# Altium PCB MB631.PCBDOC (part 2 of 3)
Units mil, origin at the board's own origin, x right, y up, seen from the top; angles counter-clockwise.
Board outline 4505 x 6805 mil, 4 copper layers (TopLayer, GND, VCC, BottomLayer); 273 components, 241 nets, 1286 pads, 636 vias.
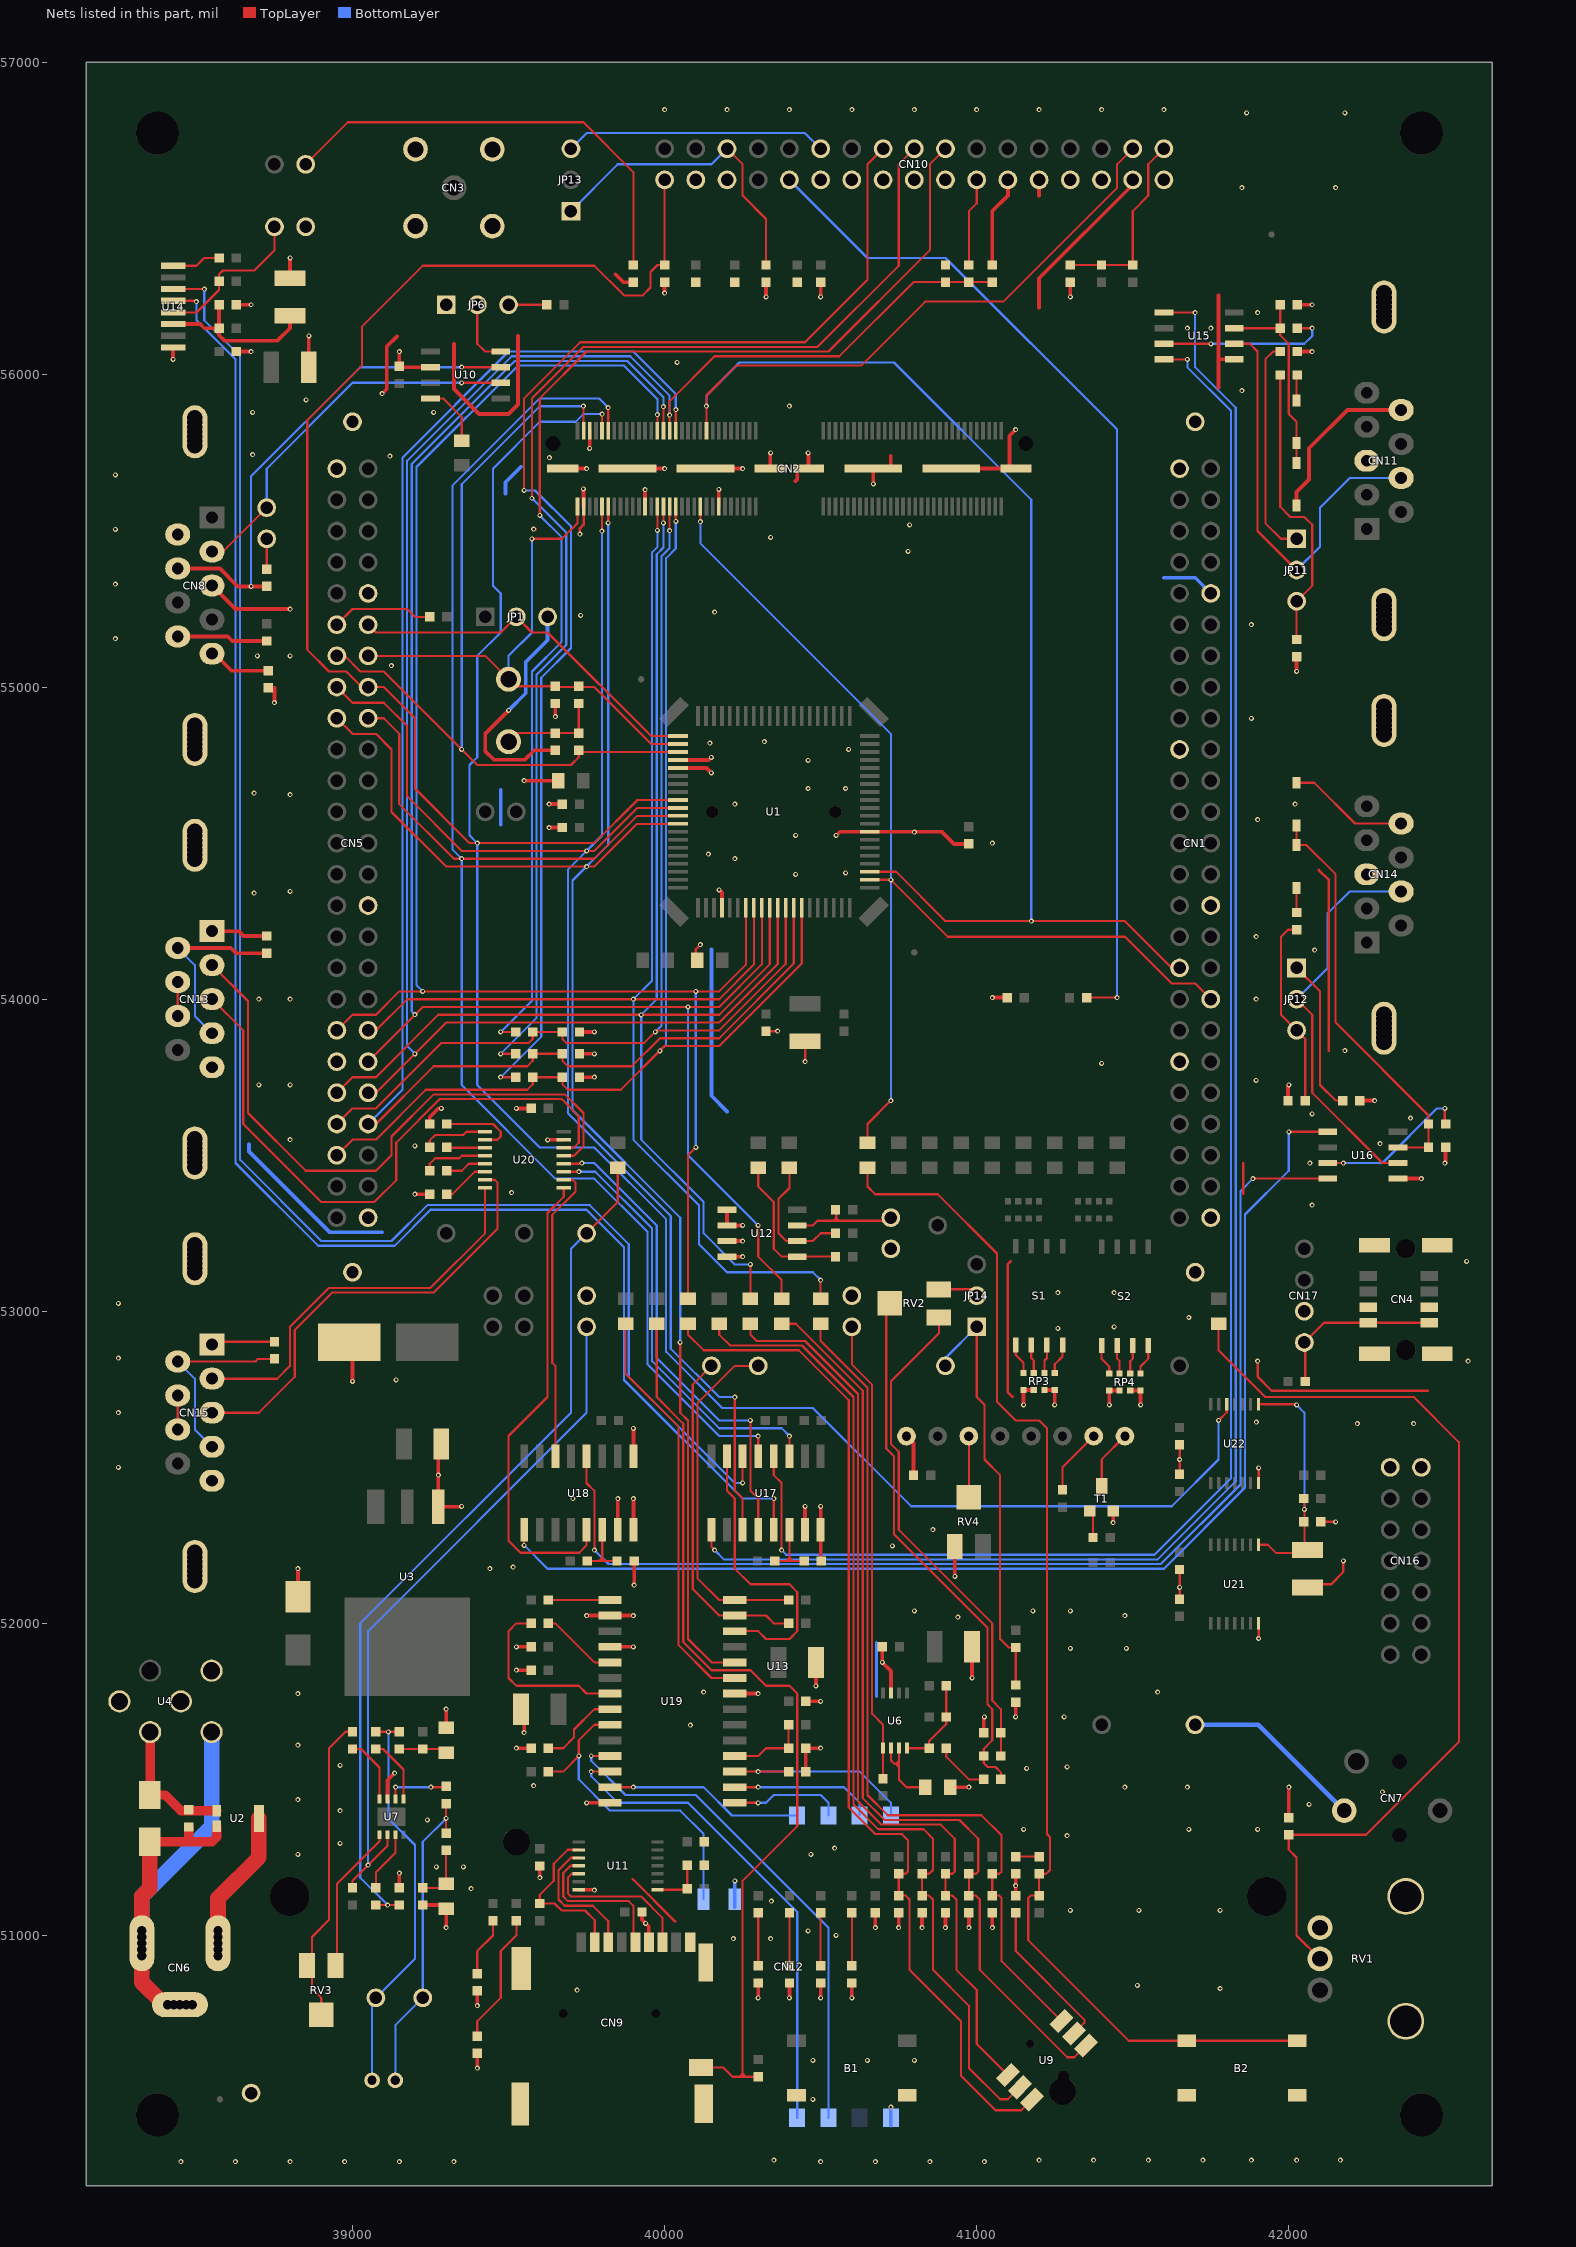
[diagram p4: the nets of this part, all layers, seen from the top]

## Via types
v1: diameter 16, hole 8, TopLayer to BottomLayer, tented both sides, 568 vias
v2: diameter 16, hole 8, TopLayer to BottomLayer, 68 vias

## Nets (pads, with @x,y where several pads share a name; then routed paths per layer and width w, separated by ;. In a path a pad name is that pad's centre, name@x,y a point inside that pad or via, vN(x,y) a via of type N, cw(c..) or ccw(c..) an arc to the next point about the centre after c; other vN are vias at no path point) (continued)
GND: B1.1 B1.4 B2.1 B2.4 C1.1 C4.2 C5.2 C6.2 C7.2 C8.2 C9.2 C10.2 C11.2 C12.2 C13.1 C16.1 C17.2 C18.2 C19.2 C20.2 C23.2 C24.1 C25.1 C26.1 C27.1 C28.1 C29.1 C30.2 C31.1 C32.1 C33.1 C34.1 C35.1 C36.1 C37.1 C38.1 C39.1 C40.1 C41.1 C42.1 C43.2 C45.2 C46.2 C47.2 C48.1 C49.2 C50.1 C53.2 C54.1 C55.2 C56.2 C57.2 C58.2 C59.1 C60.1 C61.2 C62.2 C63.2 C64.1 C65.1 C66.1 C67.1 C68.2 C69.1 C70.1 C71.2 C72.2 C73.2 C74.1 C75.1 C76.1 C77.2 CN1.1 CN1.10 CN1.19 CN1.30 CN1.39 CN1.50 CN2.4 CN2.5 CN2.24 CN2.48 CN2.G1 CN2.G2 CN2.G3 CN2.G4 CN3.1 CN3.2 CN3.3 CN3.4 CN4.3 CN4.G0 CN5.1 CN5.10 CN5.30 CN5.39 CN5.50 CN8.0 CN8.3 CN8.6 CN9.6 CN9.9 CN9.G1 CN9.G2 CN9.G3 CN9.G4 CN10.2 CN10.4 CN10.6 CN10.8 CN10.10 CN10.12 CN10.16 CN10.18 CN10.20 CN10.22 CN10.24 CN10.30 CN10.32 CN11.0 CN11.3 CN12.5 CN12.17 CN13.0 CN13.5 CN14.0 CN14.3 CN15.0 CN15.5 CN16.13 CN16.14 CN17.3 JP1.3 JP4.2 JP5.2 JP6.1 JP8.2 JP10.2 LD1.2 LD2.2 LD3.2 LD4.2 LD5.2 LD6.2 R11.1 R19.1 R25.1 R35.1 R45.1 R46.1 R48.1 R56.1 R66.1 R85.2 R90.2 R91.1 RP3.1 RP3.3 RP3.5 RP3.7 RP4.1 RP4.3 RP4.5 RP4.7 RV1.0 RV1.1 RV4.3 T1.1 TP4.1 TP11.1 TP12.1 TP13.1 TP14.1 U1.4 U1.5 U1.24 U1.48 U3.1 U4.4 U4.5 U4.6 U6.7 U7.7 U10.2 U11.7 U12.1 U12.2 U12.3 U12.4 U13.1 U14.8 U15.5 U16.5 U17.7 U17.8 U18.7 U18.8 U18.9 U19.2 U19.4 U19.14 U19.22 U20.15 U21.7 U22.7 | length 15563.9
  TopLayer w8: v1(39728.5,55490.16) 39728.5,55508.5 39740.55,55520.55 CN2.4@39740.55,55578.54 ; 39898.5,51180 40033.5,51045 ; R46.1@40100,54125 40100,54160 v1(40115,54175) ; C10.2@40325,53897.5 v1(40362.5,53897.5) ; v1(40450,53800) C7.2@40450,53865 ; 41108.5,53159.65 41100,53151.15 41100,52740.31 41115,52725.31 ; C74.1@41650,52077.5 C75.1@41650,52172.5 ; C65.1@41650,52477.5 C64.1@41650,52572.5 ; 41853.5,53376.5 41853.5,53475 ; v2(41900,52840) 41900,52790.31 41945.31,52745 42445,52745 ; v2(41903.54,51951.46) U21.7@41903.54,52000 ; U22.7@41903.54,52450 v2(41903.54,52498.54) ; C77.2@42070,52125 42134.69,52125 42175,52165.31 v2(42175,52200) ; 42095.4,54414.29 42128.5,54381.19 42128.5,53835 ; C76.1@42102.5,52325 v2(42150,52325)
  TopLayer w12: v1(38425,56050) U14.8@38425,56088.19 ; CN8.3@38550,55325 38625,55250 v1(38800,55250) ; C58.2@38625,56225 v1(38675,56225) ; C57.2@38627.5,56075 v1(38675,56075) ; v1(38750,54950) 38750,54997.5 ; C56.2@38800,56310 v1(38800,56375) ; C8.2@38825,52085 v1(38825,52175) ; C55.2@38860,56025 v1(38860,56125) ; v1(39000,52775) C11.2@39000,52900 ; v1(39095,55940) 39110,55955 39110,56091.16 39142.57,56123.73 ; U7.7@39112.2,51437.09 39112.2,51497.51 v1(39134.69,51520) ; C23.2@39150,51152.5 v1(39150,51200) ; C24.1@39150,56027.5 v1(39150,56075) ; C24.1@39152.5,56025 U10.2@39250,56025 ; v1(39200,53375) C54.1@39247.5,53375 ; R25.1@39225,51097.5 C20.2@39292.5,51097.5 ; C50.1@39247.5,53600 39247.5,53622.5 39275,53650 v1(39285,53650) ; C9.2@39275,52565 U3.1@39275,52373.82 39348.82,52373.82 v1(39350,52375) ; v1(39300,51025) C20.2@39300,51085 ; C19.2@39300,51665 v1(39300,51725) ; 39325,56100 39325,55955 39405,55875 39500,55875 39530,55905 39530,56125 ; v1(39400,50575) LD6.2@39400,50622.5 ; v1(39400,50775) LD5.2@39400,50822.5 ; v1(39500,54925) 39425,54850 39425,54795 39452.5,54767.5 39552.5,54767.5 39582.5,54797.5 C5.2@39650,54797.5 ; v1(39525,51600) C46.2@39572.5,51600 ; v1(39525,51850) C63.2@39572.5,51850 ; v1(39525,51925) C45.2@39572.5,51925 ; v1(39525,53650) C49.2@39572.5,53650 ; v1(39550,51650) C61.2@39550,51725 ; v1(39550,54700) C6.2@39660,54700 ; v1(39580,55506) v1@39585,55506 ; v1(39600,51185) C66.1@39600,51222.5 ; v1(39625,53549.41) U20.15@39676.97,53549.41 ; v1(39630,54550) C71.2@39672.5,54550 ; v1(39630,54625) C72.2@39672.5,54625 ; v1(39650,54905) C4.2@39650,54947.5 ; CN2.G1@39673.82,55700.2 39749.8,55700.2 v1(39750,55700) ; U11.7@39725,51146.46 39773.54,51146.46 v1(39775,51145) ; C36.1@39727.5,53750 v1(39775,53750) ; C35.1@39727.5,53825 v1(39775,53825) ; C34.1@39727.5,53895 v1(39775,53895) ; v1(39740,55635) 39740.55,55634.45 CN2.4@39740.55,55578.54 ; v1(39750,51425) U19.14@39825,51425 ; v1(39750,52025) v1(39900,52025) ; v1(39760,55765) 39760.24,55765.24 CN2.5@39760.24,55821.46 ; U19.4@39825,51925 v1(39900,51925) ; 39842.29,56323.02 39867.81,56297.5 C42.1@39900,56297.5 ; U18.7@39850,52300 v1(39850,52400) ; CN2.G2@39881.3,55700.2 39999.8,55700.2 v1(40000,55700) ; U18.8@39900,52300 v1(39900,52400) ; U18.9@39900,52535 v1(39900,52625) ; v1(39902.5,52122.5) R91.1@39902.5,52200 ; C12.2@39927.5,51075 39927.5,51050 39949.61,51027.89 CN9.6@39949.61,50953.35 ; CN2.24@39937.4,55578.54 v1(39937.4,55632.4) ; v1(40000,56262.5) C37.1@40000,56297.5 ; U1.5@40042.91,54740.75 40134.25,54740.75 v1(40150,54725) ; U1.4@40042.91,54766.34 40141.34,54766.34 v1(40150,54775) ; CN2.G3@40131.3,55700.2 40249.8,55700.2 v1(40250,55700) ; CN2.48@40173.62,55578.54 v1(40173.62,55633.62) ; v1(40175,54350) 40183.66,54341.34 U1.24@40183.66,54292.91 ; U12.4@40200,53175 v1(40250,53175) ; U12.3@40200,53225 v1(40250,53225) ; U12.1@40200,53325 U12.2@40200,53275 v1(40250,53275) ; U19.22@40225,51775 v1(40300,51775) ; v1(40300,50800) LD1.2@40300,50847.5 ; v1(40325,56250) C39.1@40325,56297.5 ; CN2.G4@40338.78,55700.2 40338.78,55748.78 v1(40340,55750) ; v1(40400,50800) LD2.2@40400,50847.5 ; 40419.69,55660 40425,55665.31 CN2.G1@40425,55695 ; U17.7@40450,52300 v1(40450,52375) ; C48.1@40452.5,51525 R85.2@40452.5,51600 v1(40500,51600) ; C47.2@40452.5,51750 v1(40500,51750) ; v1(40460,55750) 40461.22,55748.78 CN2.G1@40461.22,55700.2 ; v1(40485,51800) C62.2@40485,51875 ; v1(40500,50800) LD3.2@40500,50847.5 ; R90.2@40500,52202.5 v1(40500,52375) ; v1(40500,56250) R45.1@40500,56297.5 ; v1(40550,54525) 40561.02,54536.02 40888.98,54536.02 40927.5,54497.5 C73.2@40975,54497.5 ; v1(40600,50800) LD4.2@40600,50847.5 ; v1(40668.7,55651.3) CN2.G2@40668.7,55700.2 ; v1(40675,51025) C1.1@40675,51072.5 ; C13.1@40697.5,51925 v1(40697.5,51875) 40725.59,51846.91 U6.7@40725.59,51777.17 ; CN2.G2@40725,55700.2 40725,55740 ; v1(40750,51025) C26.1@40750,51072.5 ; U13.1@40775,52600 40797.5,52577.5 C30.2@40797.5,52475 ; v1(40825,51025) C25.1@40825,51072.5 ; v1(40900,51025) C27.1@40900,51072.5 ; C18.2@40915,51475 v1(40975,51475) ; CN2.G3@40918.7,55700.2 CN2.G4@41126.18,55700.2 ; v1(40929.72,52150.28) RV4.3@40929.72,52246.26 ; v1(40975,51025) C28.1@40975,51072.5 ; v1(40985,51825) C17.2@40985,51925 ; R19.1@41022.5,51650 41022.5,51697.5 v1(41025,51700) ; v1(41050,51025) C29.1@41050,51072.5 ; v1(41050,54005) C33.1@41097.5,54005 ; C32.1@41050,56352.5 41050,56525 41100,56575 CN10.12@41100,56625 ; CN2.G4@41105,55700.2 41105,55805 v1(41125,55825) ; R48.1@41125,51127.5 R11.1@41125,51197.5 ; v1(41125,51700) C16.1@41125,51747.5 ; v1(41150,52700) RP3.7@41150,52747.5 RP3.5@41183,52747.5 ; 41200,56215 41200,56309.69 CN10.4@41500,56609.69 ; 41200,56575 CN10.10@41200,56625 ; RP3.3@41217,52747.5 RP3.1@41250,52747.5 v1(41250,52700) ; v1(41300,56250) C31.1@41300,56297.5 ; v1(41425,52700) RP4.7@41425,52745.77 RP4.5@41458,52745.77 ; v1(41437.5,52322.5) T1.1@41437.5,52360 ; RP4.3@41492,52745.77 RP4.1@41525,52745.77 v1(41525,52700) ; 41775,55960 41775,56255 ; 41775,56050 U15.5@41825,56050 ; C70.1@41997.5,53675 41997.5,53722.5 v1(42000,53725) ; C68.2@42000,51377.5 v1(42000,51475) ; v1(42025,55050) C69.1@42025,55097.5 ; C59.1@42027.5,56075 v1(42075,56075) ; C43.2@42027.5,56225 v1(42075,56225) ; C60.1@42227.5,53675 v1(42275,53675) ; U16.5@42350,53425 v1(42425,53425) ; v1(42500,53475) 42502.5,53477.5 C53.2@42502.5,53525
  BottomLayer w10: 40678.5,51766.5 40678.5,51938.19
  BottomLayer w12: 38668.5,53535 38668.5,53511.5 38926.5,53253.5 39095,53253.5 ; 39475,54560 39475,54670 ; 39490,55620 39490,55656.45 39539.55,55706 ; v1(39500,54925) 39555,54980 39555,55080 39625,55150 JP1.3@39625,55225 ; 40150,54160 40150,53690.31 40200.31,53640 ; CN12.17@40225,51091.54 v1(40225,51175) ; CN12.5@40725,50390.75 v1(40725,50450) ; 41600,55350 41700,55350 CN1.10@41750,55300
  other v1: 38450,50275 38625,50275 38800,50275 38975,50275 39150,50275 39325,50275 40500,50275 40675,50275 40850,50275 41025,50275 40350,50280 41200,50280 41375,50280 41550,50280 41725,50280 41880,50280 42025,50280 42165,50280 40475,50475 40475,50600 40650,50600 40800,50600 39720,50825 40220,50990 40340,50990 40550,51000 40460,51015 39939.06,51038.44 40342.5,51110 39380,51150 41125,51160 39269,51220 39355,51220 38825,51260 40469,51260 40545,51280 38960,51295 39240,51370 38960,51400 38825,51435 41475,51475 41675,51475 39580,51480 38960,51545 38825,51610 40082.58,51673.58 38825,51775 40125,51780 39440,52175 39515,52180 39706,52400 39275,52475 38250,52500 38250,52675 39140,52780 42575,52840 38250,52850 38250,53025 42570,53160 42075,53340 39510,53380 42067.5,53475 39200,53530 42292.5,53537.5 38800,53550 42390,53619 42075,53632.5 38700,53725 38800,53725 41895,53740 41400,53794 42180,53835 38700,54000 38800,54000 41895,54000 42082.5,54157.5 41895,54200 38685,54340 38800,54345 40420,54400 40580,54405 40225,54450 40140,54465 41050,54500 40420,54525 40800,54535 41900,54575 40225,54625 42020,54625 38800,54655 38685,54660 40460,54675 40580,54675 40460,54765 40590,54800 40145,54820 40320,54825 41880,54900 39124.84,55069 38695,55100 38800,55100 38240,55155 41880,55200 39731,55230 40160,55240 38240,55330 40780,55435 40340,55480 38240,55505 40785,55520 38240,55680 39631,55735 39120,55740 38680,55745 38680,55880 39260,55880 40400,55900 38851.16,55920 41850,55950 40040,56040 41675,56150 41750,56150 41900,56200 41850,56600 42150,56600 41865,56840 42180,56840 40000,56850 40200,56850 40400,56850 40600,56850 40800,56850 41000,56850 41200,56850 41400,56850 41600,56850
  other v2: 41780,50830 41515,50840 41300,51080 41520,51080 41780,51080 41290,51320 41150,51340 41680,51340 41900,51340 42065,51420 42300,51460 41160,51535 41290,51540 41280,51700 41580,51780 41300,51920 41480,51920 40940,52020 41475,52025 40800,52040 41180,52040 41300,52040 41650,52115 40730,52248.5 40860,52300 41650,52525 42220,52640 42400,52640 41896.5,52645 41260,52945 41440,52950 41680,52980 41260,53060 41440,53060
NetB2_2: B2.2 B2.3 C2.2 R3.1 R4.2 | length 3942.8
  TopLayer w7: R4.2@40650,53460 40650,53400 40675,53375 40875,53375 41065,53185 41065,52710 41125,52650 41200,52650 41225,52625 41225,51325 41235,51315 41235,51210 41222.5,51197.5 C2.2@41200,51197.5 R3.1@41200,51127.5 41172.5,51127.5 41165,51120 41165,50985 41487.5,50662.5 B2.3@42037.5,50662.5
NetC2_1: C2.1 R11.2 | length 75
  TopLayer w7: R11.2@41125,51252.5 C2.1@41200,51252.5
NetC5_1: C5.1 R2.1 R98.2 X1.1 | length 331.4
  TopLayer w7: X1.1@39500,54825 39527.5,54852.5 R98.2@39725,54852.5 R2.1@39725,54947.5
NetC15_2: C15.2 R31.1 | length 177.5
  TopLayer w7: R31.1@40902.5,51600 40902.5,51572.5 40975,51500 C15.2@41022.5,51500
NetC19_1: C19.1 R22.1 R23.1 | length 147.5
  TopLayer w7: R23.1@39150,51597.5 C19.1@39297.5,51597.5
NetC20_1: C20.1 R24.1 R25.2 | length 175
  TopLayer w7: R25.2@39225,51152.5 C20.1@39292.5,51152.5 ; C20.1@39300,51165 R24.1@39300,51272.5
NetC21_2: C21.2 U7.5 | length 210.2
  TopLayer w7: C21.2@39075,51597.5 39097.5,51597.5 39163.39,51531.61 U7.5@39163.39,51437.09
NetC22_2: C22.2 U7.6 | length 197.6
  TopLayer w7: U7.6@39137.8,51437.09 v1(39137.8,51475) ; v1(39251.25,51475) C22.2@39297.5,51475
  BottomLayer w7: v1(39137.8,51475) v1(39251.25,51475)
NetC42_2: C42.2 JP9.2 | length 1469.7
  TopLayer w7: JP9.2@38850,56675 38985,56810 39740,56810 39900,56650 C42.2@39900,56352.5
NetC44_1: C44.1 U19.7 | length 588.6
  TopLayer w7: C44.1@39572.5,52000 39525,52000 39500,51975 39500,51825 39525,51800 39725,51800 39750,51775 U19.7@39835,51775
NetC48_2: C48.2 CN12.1 U19.17 | length 679.7
  TopLayer w7: U19.17@40225,51525 C48.2@40397.5,51525
  BottomLayer w7: v1(40300,51525) 40625,51525 40725,51425 CN12.1@40725,51384.25
NetC50_2: C50.2 U20.2 | length 252.2
  TopLayer w7: C50.2@39302.5,53600 39450,53600 39475,53575 39475,53560 39464.41,53549.41 U20.2@39425,53549.41
NetC52_1: C52.1 U20.1 | length 211.4
  TopLayer w7: C52.1@39247.5,53525 39247.5,53547.5 39265,53565 39355,53565 39365,53575 U20.1@39425,53575
NetC52_2: C52.2 U20.3 | length 121.3
  TopLayer w7: C52.2@39303.68,53523.82 U20.3@39425,53523.82
NetC54_2: C54.2 U20.6 | length 152.3
  TopLayer w7: C54.2@39302.5,53375 39320,53375 39392.05,53447.05 U20.6@39425,53447.05
NetCN6_1: CN6.1 U2.1 | length 474.2
  TopLayer w50: CN6.1@38569.09,50955 38569.09,51119.09 38700,51250 U2.1@38700,51375
NetCN6_3: C3.2 CN6.2 CN6.3 U2.2 U4.2 Z1.1 | length 1696.7
  TopLayer w30: Z1.1@38360,51300.2 38549.8,51300.2 38565,51315.39 U2.2@38565,51350 ; 38475,51300.2 C3.2@38475,51347.5
  TopLayer w50: Z1.1@38350,51315 38350,51150 38325,51125 38325,50850 38395,50780 CN6.2@38455,50780
  BottomLayer w30: CN6.3@38325,50985 CN6.3@38325,50995
  BottomLayer w50: CN6.3@38325,50985 38325,51125 38548.43,51348.43 U4.2@38548.43,51651.57
NetCN7_10: CN7.10 U5.1 | length 591.9
  BottomLayer w15: U5.1@41699.61,51675 41902.56,51675 CN7.10@42177.56,51400
NetCN9_10: CN9.10 R100.1 R101.1 | length 3012
  TopLayer w7: R101.1@39975,52960 39975,52725 40060,52640 40060,51940 40150,51850 40275,51850 40325,51800 40400,51800 40425,51775 40425,51350 40250,51175 40250,50547.5 ; CN9.10@40116.93,50576.77 40188.23,50576.77 40217.5,50547.5 R100.1@40300,50547.5 ; 40240,50547.5 40250,50557.5 40260,50547.5
NetCN10_14: CN10.14 R61.1 | length 282.9
  TopLayer w7: R61.1@40975,56352.5 40975,56525 41000,56550 CN10.14@41000,56625
NetCN10_26: CN10.26 R63.1 | length 3298.9
  TopLayer w7: R63.1@41352.5,54005 v1(41450,54005)
  BottomLayer w7: CN10.26@40400,56625 40650,56375 40900,56375 41450,55825 v1(41450,54005)
NetCN12_2: CN12.2 U19.16 | length 461.5
  TopLayer w7: U19.16@40225,51475 v1(40300,51475)
  BottomLayer w7: v1(40300,51475) 40575,51475 40625,51425 CN12.2@40625,51384.25
NetCN12_3: CN12.3 U19.15 | length 361.5
  TopLayer w7: U19.15@40225,51425 v1(40300,51425)
  BottomLayer w7: v1(40300,51425) 40325,51425 40350,51450 40500,51450 40525,51425 CN12.3@40525,51384.25
NetCN13_7: CN13.7 CN13.8 | length 109
  TopLayer w7: CN13.8@38440,53946 CN13.7@38440,54055
NetCN15_7: CN15.7 CN15.8 | length 109
  TopLayer w7: CN15.8@38440,52621 CN15.7@38440,52730
NetD1_1: CN11.9 D1.1 | length 546
  TopLayer w12: D1.1@42025,55581.5 42025,55625 42065,55665 42065,55765 42188,55888 CN11.9@42360,55888
NetD2_1: CN14.9 D2.1 | length 389.1
  TopLayer w7: D2.1@42025,54693.5 42081.5,54693.5 42212,54563 CN14.9@42360,54563
NetJP4_1: JP4.1 R27.1 U6.1 | length 1488.9
  TopLayer w7: JP4.1@40600,52950 40600,52830 40665,52765 40665,51710 40700,51675 R27.1@40700,51502.5
NetJP6_3: JP6.3 R33.1 | length 122.5
  TopLayer w7: JP6.3@39500,56225 R33.1@39622.5,56225
NetJP10_1: JP10.1 R81.1 U14.5 | length 512
  TopLayer w7: U14.5@38425,56200.39 38500.39,56200.39 38572.5,56272.5 38572.5,56322.5 38585,56335 38685,56335 38750,56400 JP10.1@38750,56475
NetJP11_1: C59.2 JP11.1 | length 703.6
  TopLayer w7: C59.2@41972.5,56075 41950,56075 41925,56050 41925,55525 41975,55475 JP11.1@42025,55475
NetJP12_1: C60.2 JP12.1 | length 499.3
  TopLayer w7: JP12.1@42025,54100 42100,54025 42100,53725 42150,53675 C60.2@42172.5,53675
NetJP13_1: C39.2 CN10.29 JP13.1 | length 1007.1
  TopLayer w7: CN10.29@40200,56725 40250,56675 40250,56575 40325,56500 C39.2@40325,56352.5
  BottomLayer w7: JP13.1@39700,56525 39850,56675 40150,56675 CN10.29@40200,56725
NetJP13_3: CN10.23 JP13.3 | length 841.4
  BottomLayer w7: JP13.3@39700,56725 39750,56775 40450,56775 CN10.23@40500,56725
NetR5_2: C68.1 R5.2 RV1.2 | length 3044.3
  TopLayer w7: R5.2@41775,52960 41775,52875 41925,52725 42400,52725 42545,52580 42545,51620 42247.5,51322.5 C68.1@42000,51322.5 42000,51275 42025,51250 42025,51000 RV1.2@42100,50925
NetR6_2: CN4.4 CN17.4 R6.2 | length 548.4
  TopLayer w7: CN17.4@42050,52900 42112.99,52962.99 CN4.4@42449.8,52962.99 ; R6.2@42052.5,52775 CN17.4@42052.5,52897.5
NetR12_1: LD4.1 R12.1 | length 170
  TopLayer w7: LD4.1@40600,50902.5 R12.1@40600,51072.5
NetR13_1: LD3.1 R13.1 | length 170
  TopLayer w7: LD3.1@40500,50902.5 R13.1@40500,51072.5
NetR14_1: LD2.1 R14.1 | length 170
  TopLayer w7: LD2.1@40400,50902.5 R14.1@40400,51072.5
NetR15_1: LD1.1 R15.1 | length 170
  TopLayer w7: LD1.1@40300,50902.5 R15.1@40300,51072.5
NetR16_1: CN5.11 R16.1 | length 328.6
  TopLayer w7: CN5.11@38950,55200 39000,55250 39175,55250 39200,55225 R16.1@39247.5,55225
NetR17_1: LD5.1 R17.1 | length 190.7
  TopLayer w7: LD5.1@39400,50877.5 39400,50950 39450,51000 R17.1@39450,51047.5
NetR18_1: LD6.1 R18.1 | length 421.8
  TopLayer w7: LD6.1@39400,50677.5 39400,50725 39475,50800 39475,50950 39525,51000 R18.1@39525,51047.5
NetR19_2: R19.2 R32.1 RV2.3 | length 1614.4
  TopLayer w7: RV2.3@40878.74,52979.72 40878.74,52928.74 40725,52775 40725,52575 40750,52550 40750,52300 41050,52000 41050,51752.5 41077.5,51725 R32.1@41077.5,51575
NetR26_1: R26.1 RV3.1 RV3.2 | length 985.7
  TopLayer w7: RV3.2@38900,50746.26 38900,50800 38870,50830 38870,50995 38925,51050 38925,51600 38977.5,51652.5 R26.1@39000,51652.5
NetR30_2: C16.2 JP14.1 R30.2 TP5.1 | length 1393.9
  TopLayer w7: JP14.1@41000,52965 41000,52725 41025,52700 41025,52525 41075,52475 41075,51950 41102.5,51922.5 R30.2@41125,51922.5 C16.2@41125,51802.5
  BottomLayer w7: TP5.1@40900,52825 40900,52850 JP14.1@41000,52950
NetR31_2: C14.1 R29.1 R31.2 U6.4 | length 293.5
  TopLayer w7: U6.4@40776.77,51600 R31.2@40847.5,51600 40847.5,51622.5 40902.5,51677.5 R29.1@40902.5,51800
NetR39_1: C25.2 R39.1 R49.2 U9.2 | length 3212.5
  TopLayer w7: R39.1@40175,52960 40175,52925 40210,52890 40440,52890 40605,52725 40605,51420 40685,51340 40830,51340 40860,51310 40860,51210 40847.5,51197.5 R49.2@40825,51197.5 C25.2@40825,51127.5 40847.5,51127.5 40860,51115 40860,50890 40975,50775 40975,50575 41075,50475 41100,50475 U9.2@41138.7,50513.7
NetR40_1: C26.2 R40.1 R50.1 U9.3 | length 3339.7
  TopLayer w7: R40.1@40075,52960 40075,52925 40125,52875 40430,52875 40590,52715 40590,51410 40675,51325 40760,51325 40780,51305 40780,51205 40772.5,51197.5 R50.1@40750,51197.5 C26.2@40750,51127.5 40772.5,51127.5 40785,51115 40785,50890 40950,50725 40950,50550 41060,50440 41142.95,50440 U9.3@41177.67,50474.73
NetR41_1: C27.2 R41.1 R51.1 U9.1 | length 3002.2
  TopLayer w7: R41.1@40275,52960 40275,52925 40295,52905 40450,52905 40620,52735 40620,51430 40695,51355 40885,51355 40930,51310 40930,51205 40922.5,51197.5 R51.1@40900,51197.5 C27.2@40900,51127.5 40922.5,51127.5 40935,51115 40935,50890 41000,50825 41000,50652.4 U9.1@41099.73,50552.67
NetR42_1: C28.2 R42.1 R52.1 U9.4 | length 3022.9
  TopLayer w7: R42.1@40375,52960 40420,52960 40635,52745 40635,51440 40705,51370 40945,51370 41005,51310 41005,51205 40997.5,51197.5 R52.1@40975,51197.5 C28.2@40975,51127.5 40997.5,51127.5 41010,51115 41010,50890 41290,50610 41312.95,50610 U9.4@41350.27,50647.33
NetR43_1: R43.1 U10.4 | length 199.9
  TopLayer w7: U10.4@39250,55925 39290,55925 39350,55865 R43.1@39350,55790
NetR44_1: C29.2 R44.1 R53.1 U9.6 | length 2781.6
  TopLayer w7: R44.1@40500,52960 40500,52905 40650,52755 40650,51450 40715,51385 41015,51385 41080,51320 41080,51205 41072.5,51197.5 R53.1@41050,51197.5 C29.2@41050,51127.5 41072.5,51127.5 41080,51120 41080,50917.6 U9.6@41272.33,50725.27
NetR48_2: R48.2 U9.5 | length 491.3
  TopLayer w7: R48.2@41125,51072.5 41125,50950 41345,50730 41345,50720 U9.5@41311.3,50686.3
NetR54_2: JP7.1 R54.2 | length 97.5
  TopLayer w7: R54.2@38725,55377.5 JP7.1@38725,55475
NetR55_2: CN8.9 R55.2 | length 291
  TopLayer w12: CN8.9@38440,55162 38600,55162 38614.5,55147.5 R55.2@38725,55147.5
NetR56_2: CN8.5 R56.2 | length 191.7
  TopLayer w12: CN8.5@38560,55105 38612.5,55052.5 R56.2@38730,55052.5
NetR62_2: CN10.15 R62.2 | length 3979.7
  TopLayer w7: v1(39475,53895) R62.2@39522.5,53895 ; v1(39600,55550) 39600,55925 39750,56075 40525,56075 40850,56400 40850,56675 CN10.15@40900,56725
  BottomLayer w7: v1(39475,53895) 39575,53995 39575,55050 39670,55145 39670,55480 v1(39600,55550)
NetR64_2: CN10.17 R64.2 | length 4026.8
  TopLayer w7: v1(39475,53825) R64.2@39522.5,53825 ; v1(39575,55605) 39575,55925 39740,56090 40490,56090 40750,56350 40750,56675 CN10.17@40800,56725
  BottomLayer w7: v1(39475,53825) 39590,53940 39590,55040 39685,55135 39685,55495 v1(39575,55605)
NetR65_2: CN10.19 R65.2 | length 4096.4
  TopLayer w7: v1(39475,53750) R65.2@39522.5,53750 ; v1(39550,55630) 39550,55925 39730,56105 40450,56105 40650,56305 40650,56675 CN10.19@40700,56725
  BottomLayer w7: v1(39475,53750) 39605,53880 39605,55030 39700,55125 39700,55515 39585,55630 v1(39550,55630)
NetR67_1: C31.2 CN10.1 R60.1 R67.1 | length 613.9
  TopLayer w7: C31.2@41300,56352.5 R60.1@41500,56352.5 41500,56525 41550,56575 41550,56675 CN10.1@41600,56725
NetR70_2: R70.2 R90.1 U17.6 | length 223.3
  TopLayer w7: R70.2@40352.5,52200 R90.1@40447.5,52200 ; 40390,52200 40400,52210 40410,52200 ; 40400,52200 U17.6@40400,52300
NetR71_2: R71.2 R91.2 U18.6 | length 223.3
  TopLayer w7: R71.2@39752.5,52200 R91.2@39847.5,52200 ; 39790,52200 39800,52210 39810,52200 ; 39800,52200 U18.6@39800,52300
NetR79_1: D3.2 R79.1 | length 79
  TopLayer w7: D3.2@42025,55918.5 R79.1@42025,55997.5
NetR79_2: C69.2 JP11.3 R79.2 | length 937
  TopLayer w7: R79.2@41972.5,56000 41972.5,55577.5 42005.55,55544.45 42050.55,55544.45 42075,55520 42075,55325 JP11.3@42025,55275 C69.2@42025,55152.5
NetR80_1: D4.2 R80.1 | length 79
  TopLayer w7: R80.1@42025,54277.5 D4.2@42025,54356.5
NetR80_2: C70.2 JP12.3 R80.2 | length 616.4
  TopLayer w7: R80.2@42025,54222.5 41997.5,54222.5 41975,54200 41975,53950 42052.5,53872.5 C70.2@42052.5,53675
NetR87_2: R87.2 U19.1 | length 197.5
  TopLayer w7: R87.2@39627.5,52075 U19.1@39825,52075
NetR88_2: R88.2 U14.1 | length 157.9
  TopLayer w7: U14.1@38425,56350 38500,56350 38525,56375 R88.2@38572.5,56375
NetR89_2: C56.1 C58.1 R89.2 U14.6 | length 541.7
  TopLayer w12: U14.6@38425,56162.99 38512.01,56162.99 38525,56150 R89.2@38572.5,56150 ; C58.1@38572.5,56225 38572.5,56127.5 38590,56110 38760,56110 38800,56150 C56.1@38800,56190
NetR92_1: CN13.4 CN13.6 R92.1 | length 610.4
  TopLayer w12: CN13.6@38440,54164 38610,54164 38626.5,54147.5 R92.1@38725,54147.5
  BottomLayer w7: CN13.6@38440,54164 38495,54109 38495,53946 CN13.4@38550,53891
NetR92_2: CN13.1 R92.2 | length 181.4
  TopLayer w12: CN13.1@38550,54218 38635,54218 38650.5,54202.5 R92.2@38725,54202.5
NetR93_1: CN15.4 CN15.6 R93.1 | length 632.1
  TopLayer w7: CN15.6@38440,52839 38689,52839 38697.5,52847.5 R93.1@38750,52847.5
  BottomLayer w7: CN15.6@38440,52839 38495,52784 38495,52621 CN15.4@38550,52566
NetR93_2: CN15.1 R93.2 | length 202.5
  TopLayer w7: CN15.1@38547.5,52902.5 R93.2@38750,52902.5
NetR104_2: R104.2 U13.7 | length 213.9
  TopLayer w7: R104.2@41275,52427.5 41275,52500 U13.7@41375,52600
NetRP4_2: RP4.2 S2.7 | length 99.6
  TopLayer w7: RP4.2@41525,52800.77 41525,52823.27 41550,52848.27 S2.7@41550,52890
NetRP4_4: RP4.4 S2.5 | length 92.5
  TopLayer w7: RP4.4@41492,52800.77 41492,52840.27 41500,52848.27 S2.5@41500,52890
NetRP4_6: RP4.6 S2.3 | length 92.5
  TopLayer w7: S2.3@41450,52890 41450,52848.27 41458,52840.27 RP4.6@41458,52800.77
NetRP4_8: RP4.8 S2.1 | length 99.6
  TopLayer w7: S2.1@41400,52890 41400,52848.27 41425,52823.27 RP4.8@41425,52800.77
NetRV2_1: JP14.2 RV2.1 | length 138.1
  TopLayer w7: RV2.1@40870.28,53070.28 40979.72,53070.28 JP14.2@41000,53050
NetRV2_2: C15.1 R32.2 RV2.2 | length 1719.6
  TopLayer w7: RV2.2@40710,53030 40710,52560 40735,52535 40735,52285 41035,51985 41035,51740 41050,51725 41050,51625 41022.5,51597.5 41022.5,51552.5 41035,51540 41060,51540 41077.5,51522.5 C15.1@41077.5,51500
NetRV3_3: RV3.3 U7.1 | length 484.5
  TopLayer w7: RV3.3@38950,50895 38950,51165 39086.61,51301.61 U7.1@39086.61,51322.91
NetRV4_2: RV4.2 U13.3 | length 196.3
  TopLayer w7: RV4.2@40975,52403.74 U13.3@40975,52600
NetS1_1: RP3.8 S1.1 | length 99.6
  TopLayer w7: S1.1@41125,52891.73 41125,52860 41150,52835 RP3.8@41150,52802.5
NetS1_3: RP3.6 S1.3 | length 92.5
  TopLayer w7: S1.3@41175,52891.73 41175,52850 41183,52842 RP3.6@41183,52802.5
NetS1_5: RP3.4 S1.5 | length 92.5
  TopLayer w7: RP3.4@41217,52802.5 41217,52842 41225,52850 S1.5@41225,52891.73
NetS1_7: RP3.2 S1.7 | length 99.6
  TopLayer w7: RP3.2@41250,52802.5 41250,52830 41275,52855 S1.7@41275,52891.73
NetT1_2: R103.1 T1.2 | length 82.5
  TopLayer w7: R103.1@41372.5,52275 T1.2@41372.5,52357.5
NetTP6_1: C23.1 R20.1 R21.2 TP6.1 | length 2815.5
  TopLayer w7: R20.1@39075,51097.5 C23.1@39150,51097.5 ; TP6.1@39750,53250 39850,53350 R21.2@39850,53460
  BottomLayer w7: v1(39112.5,51097.5) 39025,51185 39025,52000 39700,52675 39700,53200 TP6.1@39750,53250
NetU2_3: C3.1 U2.3 U4.1 Z1.2 | length 438.1
  TopLayer w30: U4.1@38351.57,51651.57 38351.57,51451.38 Z1.2@38350,51449.8 38400.2,51449.8 38450,51400 U2.3@38565,51400
NetU6_2: C18.1 U6.2 U6.3 | length 292.5
  TopLayer w7: U6.2@40725.59,51600 40725.59,51560.59 40736.18,51550 40751.18,51550 ; 40751.18,51540 40741.18,51550 40751.18,51560 ; U6.3@40751.18,51600 40751.18,51498.82 40775,51475 C18.1@40835,51475
NetU7_2: JP5.1 R28.2 U7.2 | length 2231.8
  TopLayer w7: R28.2@39000,51152.5 39000,51175 39112.2,51287.2 U7.2@39112.2,51322.91
  BottomLayer w7: v1(39050,51225) 39050,51975 39750,52675 JP5.1@39750,52950
NetU7_3: R20.2 U7.3 | length 196.4
  TopLayer w7: R20.2@39075,51152.5 39075,51202.57 39137.8,51265.37 U7.3@39137.8,51322.91
NetU7_8: R26.2 U7.8 | length 212.4
  TopLayer w7: R26.2@39000,51597.5 39027.5,51597.5 39086.61,51538.39 U7.8@39086.61,51437.09
NetU8_1: C22.1 R24.2 TP8.1 U8.1 | length 1001.7
  TopLayer w7: R24.2@39300,51327.5 C22.1@39300,51422.5
  BottomLayer w7: U8.1@39137.4,50535.63 39137.4,50712.4 TP8.1@39225,50800 39225,51300 v1(39300,51375)
NetU8_2: C21.1 R23.2 TP7.1 U8.2 | length 1284
  TopLayer w7: C21.1@39075,51652.5 R23.2@39150,51652.5
  BottomLayer w7: U8.2@39062.6,50535.63 39062.6,50787.6 39200,50925 39200,51290 39115,51375 v1(39115,51652.5)
NetU10_6: CN8.2 JP7.2 U10.6 | length 1222.3
  TopLayer w7: CN8.2@38550,55434 38584,55434 JP7.2@38725,55575 ; v1(39350,55975) U10.6@39475,55975
  BottomLayer w7: JP7.2@38725,55575 38725,55700 39000,55975 v1(39350,55975)
NetU10_7: CN8.7 R54.1 U10.7 | length 1606.3
  TopLayer w7: v1(39350,56025) U10.7@39475,56025
  TopLayer w12: CN8.7@38440,55380 38575,55380 38632.5,55322.5 R54.1@38725,55322.5
  BottomLayer w7: v1(38675,55322.5) 38675,55675 39025,56025 v1(39350,56025)
NetU10_8: JP6.2 U10.8 | length 210.4
  TopLayer w7: JP6.2@39400,56225 39400,56100 39425,56075 U10.8@39475,56075
NetU11_2: CN9.2 R57.1 U11.2 | length 513.5
  TopLayer w7: U11.2@39725,51274.41 39689.41,51274.41 39645,51230 39645,51175 39600,51130 R57.1@39600,51102.5 39647.5,51102.5 39670,51080 39745,51080 39776.38,51048.62 CN9.2@39776.38,50978.35
NetU11_3: CN9.3 U11.3 | length 430.9
  TopLayer w7: U11.3@39725,51248.82 39700,51248.82 39660,51208.82 39660,51115 39680,51095 39770,51095 39819.69,51045.31 CN9.3@39819.69,50978.35
NetU11_4: CN9.5 U11.4 | length 507.4
  TopLayer w7: U11.4@39725,51223.23 39698.23,51223.23 39675,51200 39675,51125 39690,51110 39885,51110 39900,51095 CN9.5@39900,50959.65
NetU11_5: CN9.7 U11.5 | length 529.2
  TopLayer w7: U11.5@39725,51197.64 39702.64,51197.64 39690,51185 39690,51135 39700,51125 39925,51125 39992.91,51057.09 CN9.7@39992.91,50953.35
NetU11_8: R34.1 R35.2 U11.8 | length 167
  TopLayer w7: U11.8@39976.97,51146.46 R34.1@40068.96,51146.46 ; R34.1@40072.5,51150 R35.2@40072.5,51225
NetU12_5: R38.2 R96.2 U12.5 | length 488.6
  TopLayer w7: R96.2@40300,53460 40300,53400 40350,53350 40350,53200 40375,53175 R38.2@40547.5,53175
NetU12_6: R37.2 R95.2 U12.6 | length 427.7
  TopLayer w7: R95.2@40400,53460 40400,53395 40365,53360 40365,53250 40390,53225 40475,53225 40500,53250 R37.2@40547.5,53250
NetU12_7: JP8.1 R36.2 U12.7 | length 372
  TopLayer w7: U12.7@40425,53275 40475,53275 40490,53290 JP8.1@40730,53290 ; 40540,53290 40550,53300 40560,53290 ; 40550,53290 R36.2@40550,53322.5
NetU13_8: T1.3 U13.8 | length 190.9
  TopLayer w7: T1.3@41400.5,52440 41400.5,52525.5 U13.8@41475,52600
NetU15_3: R72.1 U15.3 | length 557.9
  TopLayer w7: U15.3@41600,56100 v1(41750,56100) ; R72.1@42027.5,56150 v1(42075,56150)
  BottomLayer w7: v1(41750,56100) 42050,56100 42075,56125 v1(42075,56150)
NetU15_6: CN11.7 JP11.2 U15.6 | length 1367.5
  TopLayer w7: U15.6@41825,56100 41875,56100 41900,56075 41900,55500 JP11.2@42025,55375
  BottomLayer w7: JP11.2@42025,55375 42100,55450 42100,55575 42195,55670 CN11.7@42360,55670
NetU15_7: C43.1 D1.2 D3.1 R72.2 U15.7 | length 675.7
  TopLayer w7: U15.7@41825,56150 R72.2@41972.5,56150 ; C43.1@41972.5,56225 41972.5,56127.5 42000,56100 42000,55875 42025,55850 D1.2@42025,55718.5
NetU16_3: R73.1 U16.3 | length 495
  TopLayer w7: U16.3@42125,53475 v1(42175,53475) ; R73.1@42500,53602.5 v1(42500,53650)
  BottomLayer w7: v1(42175,53475) 42300,53475 42475,53650 v1(42500,53650)
NetU16_6: CN14.7 JP12.2 U16.6 | length 1269.3
  TopLayer w7: JP12.2@42025,54000 42075,53950 42075,53700 42300,53475 U16.6@42350,53475
  BottomLayer w7: JP12.2@42025,54000 42125,54100 42125,54275 42195,54345 CN14.7@42360,54345
NetU16_7: C53.1 D2.2 D4.1 R73.2 U16.7 | length 1316
  TopLayer w7: D4.1@42025,54493.5 42056.5,54493.5 42150,54400 42150,53925 42447.5,53627.5 C53.1@42447.5,53525 U16.7@42350,53525 ; D4.1@42025,54500 D2.2@42025,54556.5
NetU17_1: U15.1 U17.1 | length 5754
  TopLayer w7: U17.1@40150,52300 40150,52245 v1(40160,52235) ; U15.1@41600,56200 v1(41700,56200)
  BottomLayer w7: v1(40160,52235) 40190,52205 41580,52205 41830,52455 41830,55895 41700,56025 v1(41700,56200)
NetU17_4: U17.4 U20.12 | length 1550.1
  TopLayer w7: U20.12@39676.97,53472.64 39732.64,53472.64 v1(39735,53475) ; v1(40275,52650) 40275,52425 40300,52400 U17.4@40300,52300
  BottomLayer w7: v1(39735,53475) 39775,53475 39975,53275 39975,52850 40175,52650 v1(40275,52650)
NetU17_5: U14.4 U17.5 | length 5502.4
  TopLayer w7: U14.4@38425,56237.8 38497.2,56237.8 v1(38500,56235) ; U17.5@40350,52300 v1(40350,52400)
  BottomLayer w7: v1(38500,56235) 38500,56175 38625,56050 38625,53475 38890,53210 39135,53210 39250,53325 39750,53325 39870,53205 39870,52780 40250,52400 v1(40350,52400)
NetU17_11: U17.11 U20.11 | length 1387.8
  TopLayer w7: U20.11@39676.97,53447.05 v1(39725,53447.05) ; U17.11@40400,52535 v1(40400,52600)
  BottomLayer w7: v1(39725,53447.05) 39777.95,53447.05 39960,53265 39960,52840 40175,52625 40375,52625 v1(40400,52600)
NetU17_12: U15.4 U17.12 | length 5576
  TopLayer w7: U17.12@40350,52535 40350,52475 40375,52450 v1(40375,52235) ; U15.4@41600,56050 v1(41675,56050)
  BottomLayer w7: v1(40375,52235) 40390,52220 41570,52220 41815,52465 41815,55885 41675,56025 v1(41675,56050)
NetU17_14: U14.3 U17.14 | length 5405.4
  TopLayer w7: U14.3@38425,56275.2 v1@38524.8,56275.2 ; v1(40250,52450) U17.14@40250,52535
  BottomLayer w7: v1(38525,56275) 38525,56175 38640,56060 38640,53485 38900,53225 39125,53225 39240,53340 39760,53340 39885,53215 39885,52790 40225,52450 v1(40250,52450)
NetU17_15: U17.15 U19.26 | length 952.1
  TopLayer w7: U17.15@40200,52535 40200,52425 40225,52400 40225,52175 40275,52125 40400,52125 40425,52100 40425,51975 40400,51950 40325,51950 40300,51975 U19.26@40220,51975
NetU18_1: U16.1 U18.1 | length 3821.8
  TopLayer w7: v1(39550,52250) U18.1@39550,52300 ; v2(42000,53575) U16.1@42125,53575
  BottomLayer w7: v1(39550,52250) 39625,52175 41600,52175 41860,52435 41860,53310 42000,53450 v2(42000,53575)
NetU18_5: U18.5 U20.9 | length 1529.8
  TopLayer w7: U20.9@39676.97,53395.87 39676.97,53366.97 39625,53315 39625,52725 39500,52600 39500,52265 39538.5,52226.5 39726.5,52226.5 39750,52250 U18.5@39750,52300
NetU18_12: U16.4 U18.12 | length 3741.2
  TopLayer w7: U18.12@39750,52535 39750,52450 39775,52425 v1(39775,52235) ; v2(41885,53425) U16.4@42125,53425
  BottomLayer w7: v1(39775,52235) 39820,52190 41590,52190 41845,52445 41845,53385 v2(41885,53425)
NetU18_14: U18.14 U20.10 | length 953.8
  TopLayer w7: U18.14@39650,52535 39650,52825 39640,52835 39640,53308.79 39715,53383.79 39715,53411.46 39705,53421.46 U20.10@39676.97,53421.46
NetU19_5: C44.2 U19.5 | length 249.3
  TopLayer w7: C44.2@39627.5,52000 39650,52000 39775,51875 U19.5@39825,51875
NetU19_8: C46.1 U19.8 | length 273.9
  TopLayer w7: C46.1@39627.5,51600 39675,51600 39710,51635 39710,51660 39775,51725 U19.8@39835,51725
NetU19_9: CN12.18 R86.2 U19.9 | length 1044.9
  TopLayer w7: R86.2@39627.5,51525 39675,51525 v1(39725,51575) 39725,51625 39775,51675 U19.9@39825,51675
  BottomLayer w7: v1(39725,51575) 39725,51500 39825,51400 40050,51400 40125,51325 CN12.18@40125,51116.54
NetU19_11: CN12.7 U19.11 | length 1665.9
  TopLayer w7: v1(39765,51575) U19.11@39825,51575
  BottomLayer w7: v1(39765,51575) 39765,51560 39875,51450 40100,51450 40525,51025 CN12.7@40525,50415.75
NetU19_12: CN12.8 U19.12 | length 1574.4
  TopLayer w7: v1(39765,51525) U19.12@39825,51525
  BottomLayer w7: v1(39765,51525) 39765,51510 39850,51425 40075,51425 40425,51075 CN12.8@40425,50415.75
NetU19_13: CN12.4 U19.13 | length 634.1
  TopLayer w7: U19.13@39825,51475 v1(39900,51475)
  BottomLayer w7: v1(39900,51475) 40125,51475 40215.75,51384.25 CN12.4@40421.5,51384.25
NetU19_18: R84.2 R85.1 U19.18 | length 257.9
  TopLayer w7: U19.18@40225,51575 40300,51575 40325,51600 R85.1@40397.5,51600 R84.2@40397.5,51675
NetU19_23: R76.2 U19.23 | length 1323.9
  TopLayer w7: R76.2@39875,52960 39875,52800 40045,52630 40045,51930 40150,51825 U19.23@40225,51825
NetU19_27: R83.2 TP10.1 U19.27 | length 1092.9
  TopLayer w7: TP10.1@40150,52825 40090,52765 40090,52110 40175,52025 40325,52025 40350,52000 R83.2@40397.5,52000
NetU19_28: R82.2 TP9.1 U19.28 | length 1126.2
  TopLayer w7: TP9.1@40300,52825 40225,52825 40105,52705 40105,52145 40175,52075 R82.2@40397.5,52075
NetU20_4: C51.1 U20.4 | length 210.7
  TopLayer w7: C51.1@39247.5,53450 39247.5,53472.5 39265,53490 39341.77,53490 39350,53498.23 U20.4@39425,53498.23
NetU20_5: C51.2 U20.5 | length 131.9
  TopLayer w7: C51.2@39302.5,53450 39350,53450 39372.64,53472.64 U20.5@39425,53472.64
NetU20_7: CN15.3 U20.7 | length 1437.9
  TopLayer w7: CN15.3@38550,52675 38700,52675 38815,52790 38815,52940 38935,53060 39260,53060 39465,53265 39465,53411.46 39455,53421.46 U20.7@39425,53421.46
NetU20_8: CN15.2 U20.8 | length 1287.1
  TopLayer w7: CN15.2@38550,52784 38759,52784 38800,52825 38800,52950 38925,53075 39250,53075 39425,53250 U20.8@39425,53395.87
NetU20_13: CN13.2 U20.13 | length 2017
  TopLayer w7: CN13.2@38550,54109 38665,53994 38665,53635 38850,53450 39075,53450 39125,53500 39125,53560 39260,53695 39680,53695 39740,53635 39740,53528.23 39710,53498.23 U20.13@39676.97,53498.23
NetU20_14: CN13.3 U20.14 | length 1989.5
  TopLayer w7: CN13.3@38550,54000 38650,53900 38650,53600 38900,53350 39070,53350 39140,53420 39140,53540 39280,53680 39670,53680 39725,53625 39725,53540 39708.82,53523.82 U20.14@39676.97,53523.82
NetU22_8: C76.2 C77.1 R75.1 U21.8 U22.8 | length 789
  TopLayer w7: U21.8@41903.54,52251.97 41933.03,52251.97 41960,52225 42035,52225 42050,52240 R75.1@42050,52397.5 ; U22.8@41903.54,52701.97 42023.03,52701.97 v2(42025,52700)
  BottomLayer w7: v2(42025,52700) 42050,52675 v2(42050,52365)
PA0: CN5.12 JP1.2 U1.1 | length 1182.2
  TopLayer w7: CN5.12@39050,55200 39075,55175 39475,55175 JP1.2@39525,55225 39575,55175 39625,55175 39956.89,54843.11 U1.1@40042.91,54843.11
PA1: C4.1 CN2.2 CN5.14 R2.2 U1.2 X1.2 | length 1810.1
  TopLayer w7: CN5.14@39050,55100 39425,55100 39522.5,55002.5 C4.1@39650,55002.5 ; v1(39575,55475) 39670.87,55475 39720.87,55525 CN2.2@39720.87,55578.54 ; C4.1@39650,55000 39775,55000 39957.48,54817.52 U1.2@40042.91,54817.52
  BottomLayer w7: X1.2@39500,55025 39500,55100 39575,55175 v1(39575,55475)
PA2: CN2.3 CN5.13 R98.1 U1.3 | length 2684.8
  TopLayer w7: CN5.13@38950,55100 38975,55100 39025,55050 39100,55050 39400,54750 39700,54750 39725,54775 R98.1@39725,54791.93 ; R98.1@39726.93,54791.93 U1.3@40042.91,54791.93 ; CN2.3@39740.55,55821.46 v1@39740.55,55899.45
  BottomLayer w7: v1(39350,54800) 39350,55650 39600,55900 v1(39740,55900)
PA3: C37.2 CN2.9 CN5.16 CN10.34 U1.9 U22.12 | length 10118.9
  TopLayer w7: CN2.9@39799.61,55821.46 v1(39799.61,55874.61) ; CN10.34@40000,56625 C37.2@40000,56352.5 39977.5,56352.5 39955,56330 39955,56280 39930,56255 39870,56255 39775,56350 39225,56350 39030,56155 39030,56030 38855,55855 38855,55120 38925,55050 38980,55050 39030,55000 39100,55000 39200,54900 39200,54675 39375,54500 39775,54500 39913.39,54638.39 U1.9@40042.91,54638.39 ; v2(41775,52650) 41801.18,52676.18 U22.12@41801.18,52701.97
  BottomLayer w7: v1(39799.61,55874.61) 39739.61,55874.61 39715,55850 39600,55850 39450,55700 39450,55325 39475,55300 39475,55175 39400,55100 39400,54775 39375,54750 39375,54525 v1(39400,54500) 39400,53725 39600,53525 39775,53525 40005,53295 40005,52870 40185,52690 40475,52690 40790,52375 41625,52375 41775,52525 v2(41775,52650)
PA4: CN2.10 CN5.15 U1.10 U17.3 | length 5084.7
  TopLayer w7: CN5.15@38950,55000 39000,54950 39100,54950 39175,54875 39175,54650 39350,54475 39775,54475 39912.8,54612.8 U1.10@40042.91,54612.8 ; v1@39799.61,55499.61 CN2.10@39799.61,55578.54 ; v1(40225,52725) 40225,52425 40250,52400 U17.3@40250,52300
  BottomLayer w7: v1(39799.21,55500) 39799.21,54524.21 39690,54415 39690,53635 40020,53305 40020,52880 40175,52725 v1(40225,52725)
  other v1: 39750.21,54475.21
PA5: CN2.11 CN5.18 U1.11 U17.13 | length 5732
  TopLayer w7: CN5.18@39050,54900 39100,54900 39150,54850 39150,54625 39325,54450 39775,54450 39912.2,54587.2 U1.11@40042.91,54587.2 ; CN2.11@39819.29,55821.46 v1(39819.29,55895.71) ; U17.13@40300,52535 v1(40300,52600)
  BottomLayer w7: v1(39819.29,55895.71) 39790,55925 39600,55925 39320,55645 39320,54480 v1(39350,54450) 39350,53725 39650,53425 39775,53425 39945,53255 39945,52830 40175,52600 v1(40300,52600)
PA6: CN2.12 CN5.17 U1.12 U19.24 | length 5473.6
  TopLayer w7: CN5.17@38950,54900 39000,54850 39075,54850 39125,54800 39125,54600 39300,54425 39775,54425 39911.61,54561.61 U1.12@40042.91,54561.61 ; v1(39819.29,55525.71) CN2.12@39819.29,55578.54 ; v1(40050,52900) 40050,52675 40075,52650 40075,51950 40150,51875 U19.24@40225,51875
  BottomLayer w7: v1(39819.29,55525.71) 39819.29,54494.29 39705,54380 39705,53645 40050,53300 v1(40050,52900)
  other v1: 39750,54425
PB0: C36.2 CN2.34 CN5.45 R65.1 U1.34 | length 3747.1
  TopLayer w7: CN5.45@38950,53500 39000,53550 39075,53550 39235,53710 39560,53710 39577.5,53727.5 R65.1@39577.5,53750 C36.2@39672.5,53750 39672.5,53727.5 39690,53710 39860,53710 40000,53850 40175,53850 40439.57,54114.57 U1.34@40439.57,54292.91 ; v1(40035.83,55530.83) CN2.34@40035.83,55578.54
  BottomLayer w7: v1(39984.65,53834.65) 40005,53855 40005,55413.06 40035.83,55443.89 v1(40035.83,55530.83)
PB1: C35.2 CN2.33 CN5.44 R64.1 U1.33 | length 5186.5
  TopLayer w7: CN5.44@39050,53600 39075,53600 39260,53785 39560,53785 39577.5,53802.5 R64.1@39577.5,53825 C35.2@39672.5,53825 39672.5,53802.5 39690,53785 39895,53785 39985,53875 40175,53875 40413.98,54113.98 U1.33@40413.98,54292.91 ; CN2.33@40035.83,55821.46 v1(40035.83,55889.17)
  BottomLayer w7: CN5.44@39050,53600 39160,53710 39160,55735 39500,56075 39900,56075 40035.83,55939.17 v1(40035.83,55889.17)
PB2: C34.2 CN2.32 CN5.43 R62.1 U1.32 | length 3588.3
  TopLayer w7: CN5.43@38950,53600 39000,53650 39075,53650 39285,53860 39565,53860 39577.5,53872.5 R62.1@39577.5,53895 C34.2@39672.5,53895 39672.5,53872.5 39685,53860 39935,53860 39975,53900 40175,53900 40388.39,54113.39 U1.32@40388.39,54292.91 ; v1(40016.14,55501.14) CN2.32@40016.14,55578.54
  BottomLayer w7: v1(39970.22,53895.22) 39990,53915 39990,55419.27 40016.14,55445.42 v1(40016.14,55501.14)
PB3: C32.2 CN2.31 CN5.42 R61.2 R66.2 U1.31 | length 5955.6
  TopLayer w7: CN5.42@39050,53700 39075,53700 39300,53925 40175,53925 40362.8,54112.8 U1.31@40362.8,54292.91 ; CN2.31@40016.14,55821.46 40016.14,55916.14 40160,56060 40560,56060 40797.5,56297.5 C32.2@41050,56297.5
  BottomLayer w7: v1(39200,53825) 39175,53850 39175,55725 39510,56060 39890,56060 40016.14,55933.86 v1(40016.14,55871.14)
PB4: CN2.30 CN5.41 R41.2 U1.30 | length 4481.1
  TopLayer w7: CN5.41@38950,53700 39000,53750 39075,53750 39275,53950 40175,53950 40337.2,54112.2 U1.30@40337.2,54292.91 ; v1(39996.46,55526.46) CN2.30@39996.46,55578.54 ; R41.2@40275,53040 v1(40275,53150)
  BottomLayer w7: v1(39996.46,55526.46) 39996.46,55446.94 39975,55425.49 39975,54000 v1(39925,53950) 39925,53550 40125,53350 40125,53250 40225,53150 v1(40275,53150)
PB5: CN2.29 CN5.40 R42.2 U1.29 | length 5498.7
  TopLayer w7: CN5.40@39050,53800 39225,53975 40175,53975 40311.61,54111.61 U1.29@40311.61,54292.91 ; CN2.29@39996.46,55821.46 v1(39996.46,55898.54) ; v1(40300,53275) 40300,53175 40375,53100 R42.2@40375,53040
  BottomLayer w7: v1(39200.2,53950.2) 39190,53960.4 39190,55715 39520,56045 39880,56045 39996.46,55928.54 v1(39996.46,55898.54) ; v1(40075,53975) 40075,53500 v1(40300,53275)
PB6: CN2.28 CN5.38 R44.2 U1.28 | length 4485.3
  TopLayer w7: CN5.38@39050,53900 39075,53900 39175,54000 40175,54000 40286.02,54111.02 U1.28@40286.02,54292.91 ; v1(39976.77,55501.77) CN2.28@39976.77,55578.54 ; R44.2@40500,53040 v1(40500,53100)
  BottomLayer w7: v1(39976.77,55501.77) 39976.77,55448.47 39960,55431.7 39960,54060 v1(39900,54000) 39900,53550 40110,53340 40110,53215 40200,53125 40475,53125 v1(40500,53100)
PB7: CN2.27 CN5.37 R40.2 U1.27 | length 5316.1
  TopLayer w7: CN5.37@38950,53900 39000,53950 39075,53950 39150,54025 40175,54025 40260.43,54110.43 U1.27@40260.43,54292.91 ; CN2.27@39976.77,55821.46 v1(39976.77,55873.23) ; R40.2@40075,53040 40075,53500 v1(40100,53525)
  BottomLayer w7: v1(39225,54025) 39205,54045 39205,55705 39530,56030 39870,56030 39976.77,55923.23 v1(39976.77,55873.23) ; v1(40100,53525) v1(40100,54025)
PC0: CN1.36 CN2.42 R4.1 U1.42 | length 3573.8
  TopLayer w7: v1(40114.57,55530.43) CN2.42@40114.57,55578.54 ; R4.1@40650,53540 40650,53600 v1(40725,53675) ; U1.42@40657.09,54382.48 v1(40725,54382.48) 40907.48,54200 41475,54200 41625,54050 41700,54050 CN1.36@41750,54000
  BottomLayer w7: v1(40114.57,55530.43) 40114.57,55460.43 40725,54850 v1(40725,53675)
PC1: CN1.33 CN2.43 CN10.3 U1.43 | length 5621.6
  TopLayer w7: CN2.43@40134.25,55821.46 40134.25,55934.25 40230,56030 40630,56030 40835,56235 41085,56235 41450,56600 41450,56675 CN10.3@41500,56725 ; U1.43@40657.09,54408.07 40741.93,54408.07 40900,54250 41475,54250 41625,54100 CN1.33@41650,54100
  BottomLayer w7: v1(40134.25,55900) 40134.25,55934.25 40240,56040 40735,56040 41175,55600 v1(41175,54250)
